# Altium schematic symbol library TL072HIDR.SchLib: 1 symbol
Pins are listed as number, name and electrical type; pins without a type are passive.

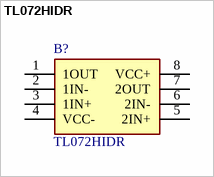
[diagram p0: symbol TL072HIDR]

## TL072HIDR
designator B?
Dual-channel low input bias current standard op amp; Manufacturer_Name: Texas Instruments; Geometry.Height: 1.75mm
footprint SOIC127P600X175-8N
pins: 1 1OUT, 2 1IN-, 3 1IN+, 4 VCC-, 5 2IN+, 6 2IN-, 7 2OUT, 8 VCC+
